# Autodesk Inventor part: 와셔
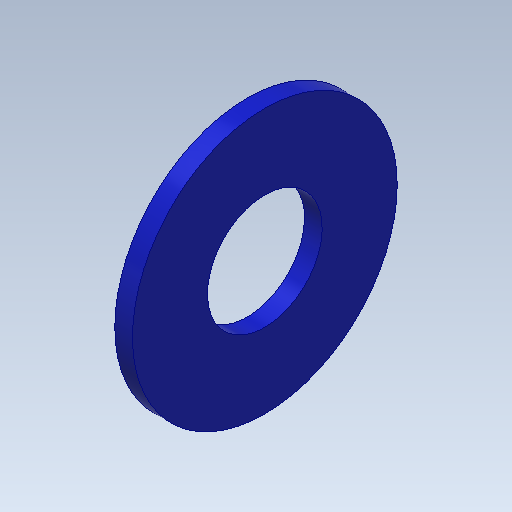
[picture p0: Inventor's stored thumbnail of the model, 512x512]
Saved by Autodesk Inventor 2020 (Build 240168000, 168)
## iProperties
Created: 2015-12
Part Number: 와셔
Material: 스테인리스강
Document SubType Name: Modeling
Designer: mduedu
Density: 8.08 g/cm^3
Appearance: 파란색 - 벽 페인트 - 광택
Author: mduedu
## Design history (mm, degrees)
sketch "스케치1"
  geometry: C1 r 3.25 at (0, 0); C2 r 7.5 at (0, 0); 1 further point
  constraints: 2 centre point, 2 coincident
  dimensions: "d0" = 6.5 diameter of C1; "d1" = 15 diameter of C2
extrude "돌출1" new body sketch "스케치1" stored distance "d2" = 1; taper "d3" = 0 deg
node "솔리드1"
